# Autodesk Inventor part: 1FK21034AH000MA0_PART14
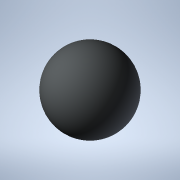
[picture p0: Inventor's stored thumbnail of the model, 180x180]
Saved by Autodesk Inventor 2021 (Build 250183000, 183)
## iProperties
Created: 2025-04
Part Number: 1FK21034AH000MA0_PART14
Material: Generic
Catalog Web Link: www.3dfindit.com
Description: -Servo synchronous motor
Document SubType Name: Modeling
Designer: psAdmin
Mass: 0.113097 g
Surface Area: 1.13097 cm^2
Volume: 0.113097 cm^3
Density: 1 g/cm^3
Appearance: PSOLRGB-212-217-219
Category: PARTsolutions
Title: 1FK21034AH000MA0_PART14
Author: Cadenas PARTsolutions
Comments: Servo synchronous motor
Sending System: PARTsolutions
Preprocessor: ST-DEVELOPER v19.3
PSOL_IDENT_0: {$CADENAS_DATA/23d-libs/siemens_ag/_cat_/ec/b7/1fk21034ah000ma0.prj},216 {VTYP=3D},{NB=1FK21034AH000
PSOL_IDENT_1: MA0_PART14},{LINA=1FK21034AH000MA0_PART14},{NN=1FK21034AH000MA0_PART14},{NOPRJ=TRUE},{DATE=19.08.202
PSOL_IDENT_2: 5 14:01:05},{GEOMDATE=30.07.2025 02:01:02},{VERSION=},{LINEID=10},{WBVAR=},{WBNUMERIC=}  {NB=1FK2103
PSOL_IDENT_3: 4AH000MA0_PART14},{LINA=1FK21034AH000MA0_PART14},{KT=DUMMY},{PREVIEW=../../../_pool_/7c/50/p_d211_xx
PSOL_IDENT_4: _00932j.png},{DESCSHORT=SIMOTICS S-1FK2 HD, SINAMICS S210 3AC 400V-480V, 1.01 Nm, 4500 rpm},{DESCLON
PSOL_IDENT_5: G=SIMOTICS S-1FK2 HD servo motor M0=1.27 Nm; PN = 0.48 kW at nN=4500 rpm (380-480 V); PN = 0.3 kW at
PSOL_IDENT_6: nN=2500 rpm (200-240 V); degree of protection IP64; cylindrical shaft D14 x 30 mm; absolute encoder
PSOL_IDENT_7: 22-bit + 12-bit multiturn (encoder AM22DQC); with OCC interface; plug size M17, rotatable; SIMOTICS
PSOL_IDENT_8: S-1FK2 servomotorfor a wide range of uses in industrial environments. SIMOTICS S‑1FK2 servomotors a
PSOL_IDENT_9: re compact synchronous motors with a high dynamic performance that set themselves apart as a result
PSOL_IDENT_10: of their high power density, degree of protection and overload capability. The motors are available
PSOL_IDENT_11: in two variants: as High Dynamic variant (highest dynamic performance as a result of the low intrins
PSOL_IDENT_12: ic moment of inertia for applications demanding a high dynamic performance with low moved masses) -
PSOL_IDENT_13: and as Compact variant (precise and stable closed-loop control for medium up to large moved masses a
PSOL_IDENT_14: s a result of a medium intrinsic moment of inertia). SIMOTICSS‑1FK2 servomotors fully exploit their
PSOL_IDENT_15: strengths in a system with the SINAMICSS210 frequency converter and simple connection using the one
PSOL_IDENT_16: cable connection (OCC). Advantages include the short control and positioning times, fast and precise
PSOL_IDENT_17: correction of disturbing quantities as well as stable control with a high dynamic performance. The
PSOL_IDENT_18: servo motors can be configured to address a wide range of requirements. For example with and without
PSOL_IDENT_19: holding brake, IP64 or IP65 degree of protection, singleturn or multiturn absolute encoders - to na
PSOL_IDENT_20: me just a few. Further, the servomotors are available in different shaft heights extending from 20 t
PSOL_IDENT_21: o 100. A shaft sealing ring is available to achieve an IP65 degree of protection and for subsequent
PSOL_IDENT_22: mounting at the motor or as spare part. SIMOTICS - the optimum motor for each and every motion contr
PSOL_IDENT_23: ol application.},{INTNO=4034106444822},{SUPPLIERALTNO=1FK2103-4AH00-0MA0},{MANUID=1FK21034AH000MA0},
PSOL_IDENT_24: {MANUNAME=Siemens},{MANUTYPEDESC=SYNCHRONOUS MOTOR 1FK2 HD 1,27 NM},{AAU732=SIMOTICS},{AAO057=S-1FK2
PSOL_IDENT_25: },{AAU734=SIMOTICS S-1FK2 HD servo motor M0=1.27 Nm; PN = 0.48 kW at nN=4500 rpm (380-480 V); PN = 0
PSOL_IDENT_26: .3 kW at nN=2500 rpm (200-240 V); degree of protection IP64; cylindrical shaft D14 x 30 mm; absolute
PSOL_IDENT_27: encoder 22-bit + 12-bit multiturn (encoder AM22DQC); with OCC interface; plug size M17, rotatable;}
PSOL_IDENT_28: ,{AAW338=SYNCHRONOUS MOTOR 1FK2 HD 1,27 NM},{AAO742=SIMOTICS},{AAO663=4034106444822},{NOCUPEROU=1},{
PSOL_IDENT_29: PRICEQUANTITY=1},{QUANTITYMIN=1},{QUANTITYINT=1},{CTN=85015100},{COO=RO},{AAO676=1FK2103-4AH00-0MA0}
PSOL_IDENT_30: ,{AAO677=Siemens AG},{ORDERUNIT=C62},{CONTENTUNIT=C62}
NB: 1FK21034AH000MA0_PART14
NT: Servo synchronous motor
NBSYN: $MANUID._PART14
LINA: 1FK21034AH000MA0_PART14
CATALOG: SIEMENS
PREVIEW: ../../../_pool_/7c/50/p_d211_xx_00932j.png
DESCSHORT: SIMOTICS S-1FK2 HD, SINAMICS S210 3AC 400V-480V, 1.01 Nm, 4500 rpm
DESCLONG: SIMOTICS S-1FK2 HD servo motor M0=1.27 Nm; PN = 0.48 kW at nN=4500 rpm (380-480 V); PN = 0.3 kW at nN=2500 rpm (200-240 V); degree of protection IP64; cylindric
INTNO: 4034106444822
SUPPLIERALTNO: 1FK2103-4AH00-0MA0
MANUID: 1FK21034AH000MA0
MANUNAME: Siemens
MANUTYPEDESC: SYNCHRONOUS MOTOR 1FK2 HD 1,27 NM
AAU732: SIMOTICS
AAO057: S-1FK2
AAU734: SIMOTICS S-1FK2 HD servo motor M0=1.27 Nm; PN = 0.48 kW at nN=4500 rpm (380-480 V); PN = 0.3 kW at nN=2500 rpm (200-240 V); degree of protection IP64; cylindric
AAW338: SYNCHRONOUS MOTOR 1FK2 HD 1,27 NM
AAO742: SIMOTICS
AAO663: 4034106444822.0
NOCUPEROU: 1
PRICEQUANTITY: 1
QUANTITYMIN: 1
QUANTITYINT: 1
CTN: 85015100
COO: RO
ARTICLENO: 1FK21034AH000MA0_PART14
BOMINFO: 1FK21034AH000MA0_PART14
CREATOR: CADENAS GmbH
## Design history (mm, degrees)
feature "2025_04_17_15_01_37_0314"
body "Solid1"
